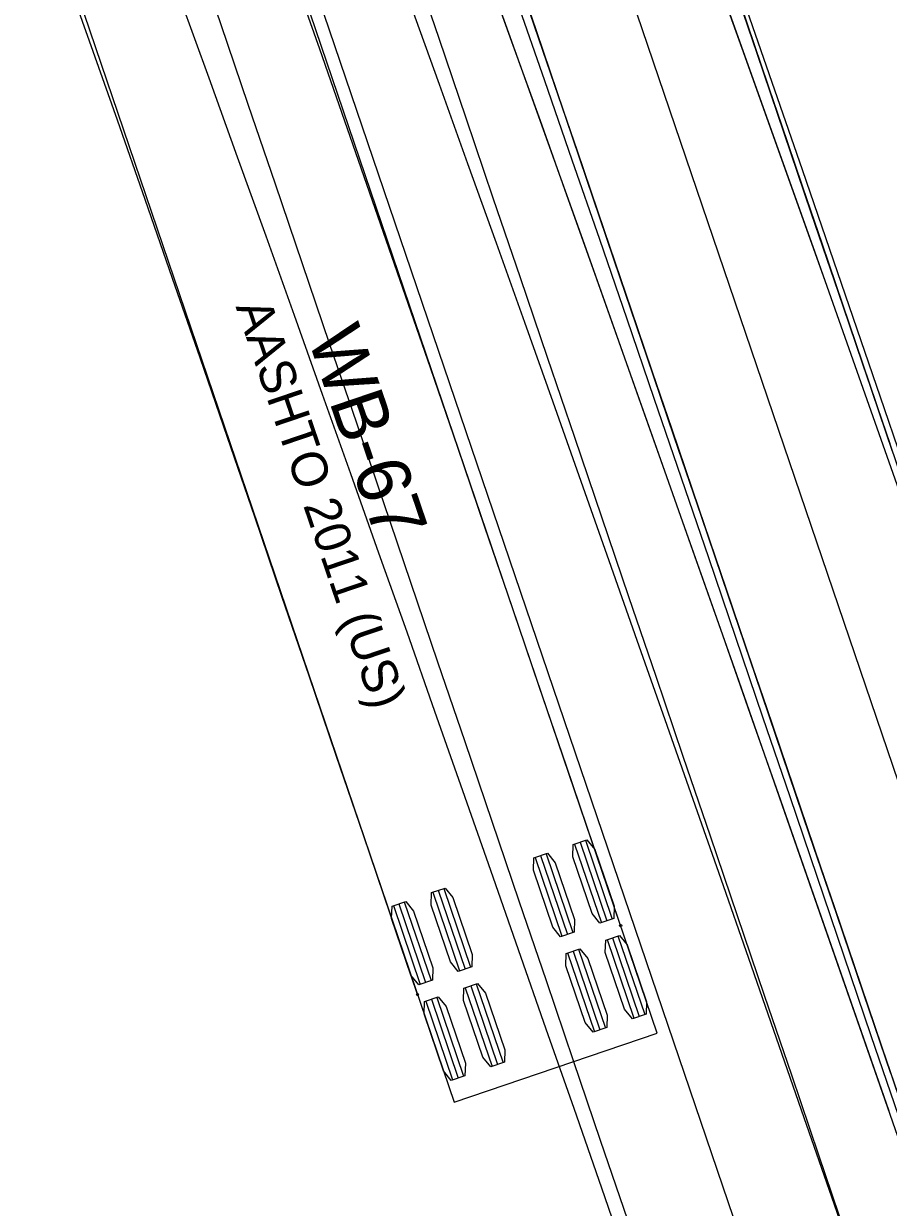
# Model space of a CAD drawing. Extents: x 916040 to 917457, y 328936 to 330267.
# Drawn here: x 916812.6 to 916846.87, y 329207.57 to 329254.51 of the extents above; entities that cross this region are included whole.
import ezdxf

# ---------------------------------------------------------------- set-up
doc = ezdxf.new("R2010")
doc.units = 0
for name, color, linetype in [('EB_RightontoSaco_WB67_v2', 7, 'Continuous'), ('NB_LeftontoRoute25_WB67', 7, 'Continuous'), ('NB_RightontoRoute25_WB67', 7, 'Continuous'), ('NB_ThruontoManchester_WB67', 7, 'Continuous'), ('SB_ThruontonSacoRd_WB67', 7, 'Continuous')]:
    doc.layers.add(name, color=color, linetype=linetype)

msp = doc.modelspace()

# ---------------------------------------------------------------- linework, layer by layer
at = {"layer": 'EB_RightontoSaco_WB67_v2'}
msp.add_line((916815.816, 329280.442), (916864.811, 329136.285), dxfattribs=at)
for points in [[(916819.347, 329257.622), (916820.42, 329254.467), (916821.492, 329251.31), (916822.565, 329248.153), (916823.639, 329244.995), (916824.712, 329241.836), (916825.786, 329238.677), (916826.86, 329235.518), (916827.933, 329232.358), (916829.007, 329229.198), (916830.081, 329226.038), (916831.156, 329222.878), (916832.23, 329219.717), (916833.304, 329216.557), (916834.378, 329213.396), (916835.452, 329210.235), (916836.527, 329207.074)], [(916827.973, 329257.101), (916829.049, 329253.935), (916830.125, 329250.77), (916831.201, 329247.605), (916832.276, 329244.441), (916833.351, 329241.277), (916834.427, 329238.114), (916835.502, 329234.951), (916836.577, 329231.788), (916837.651, 329228.626), (916838.726, 329225.463), (916839.801, 329222.301), (916840.876, 329219.139), (916841.95, 329215.977), (916843.025, 329212.815), (916844.1, 329209.653), (916845.174, 329206.492)], [(916818.803, 329255.495), (916819.938, 329252.362), (916821.068, 329249.227), (916822.195, 329246.09), (916823.319, 329242.952), (916824.438, 329239.811), (916825.555, 329236.67), (916826.669, 329233.527), (916827.78, 329230.382), (916828.889, 329227.236), (916829.995, 329224.09), (916831.099, 329220.942), (916832.2, 329217.793), (916833.3, 329214.643), (916834.399, 329211.493), (916835.495, 329208.341), (916836.59, 329205.189)], [(916827.931, 329255.252), (916829.066, 329252.106), (916830.196, 329248.96), (916831.323, 329245.812), (916832.446, 329242.663), (916833.566, 329239.513), (916834.682, 329236.362), (916835.796, 329233.211), (916836.906, 329230.059), (916838.015, 329226.906), (916839.121, 329223.752), (916840.224, 329220.598), (916841.326, 329217.444), (916842.426, 329214.288), (916843.524, 329211.133), (916844.62, 329207.977), (916845.715, 329204.821)]]:
    msp.add_lwpolyline(points, dxfattribs=at)
at = {"layer": 'NB_LeftontoRoute25_WB67'}
msp.add_line((916922.624, 329002.695), (916826.941, 329284.223), dxfattribs=at)
for points in [[(916820.466, 329308.249), (916821.712, 329305.145), (916822.946, 329302.037), (916824.17, 329298.925), (916825.385, 329295.81), (916826.59, 329292.692), (916827.786, 329289.571), (916828.974, 329286.447), (916830.154, 329283.321), (916831.327, 329280.192), (916832.494, 329277.061), (916833.654, 329273.929), (916834.808, 329270.795), (916835.956, 329267.659), (916837.1, 329264.521), (916838.238, 329261.382), (916839.372, 329258.242), (916840.502, 329255.101), (916841.628, 329251.958), (916842.75, 329248.815), (916843.869, 329245.67), (916844.984, 329242.525), (916846.097, 329239.379), (916847.206, 329236.232)], [(916822.723, 329307.431), (916823.938, 329304.292), (916825.132, 329301.146), (916826.306, 329297.992), (916827.459, 329294.831), (916828.592, 329291.662), (916829.704, 329288.486), (916830.796, 329285.304), (916831.875, 329282.131), (916832.953, 329278.96), (916834.03, 329275.792), (916835.106, 329272.626), (916836.182, 329269.461), (916837.258, 329266.298), (916838.332, 329263.135), (916839.407, 329259.974), (916840.481, 329256.813), (916841.555, 329253.654), (916842.629, 329250.494), (916843.702, 329247.336), (916844.776, 329244.177), (916845.849, 329241.019), (916846.923, 329237.861)], [(916831.852, 329257.343), (916832.923, 329254.192), (916833.994, 329251.039), (916835.066, 329247.886), (916836.138, 329244.733), (916837.21, 329241.579), (916838.282, 329238.424), (916839.354, 329235.27), (916840.426, 329232.115), (916841.498, 329228.96), (916842.571, 329225.805), (916843.643, 329222.649), (916844.716, 329219.494), (916845.788, 329216.338), (916846.861, 329213.183), (916847.933, 329210.027)], [(916831.376, 329255.36), (916832.502, 329252.229), (916833.624, 329249.096), (916834.743, 329245.961), (916835.859, 329242.825), (916836.972, 329239.687), (916838.082, 329236.548), (916839.189, 329233.408), (916840.294, 329230.267), (916841.397, 329227.124), (916842.498, 329223.981), (916843.597, 329220.837), (916844.693, 329217.692), (916845.789, 329214.546), (916846.882, 329211.399)]]:
    msp.add_lwpolyline(points, dxfattribs=at)
at = {"layer": 'NB_RightontoRoute25_WB67'}
msp.add_line((916922.624, 329002.695), (916826.941, 329284.223), dxfattribs=at)
for points in [[(916847.795, 329236.064), (916846.717, 329239.226), (916845.637, 329242.389), (916844.554, 329245.55), (916843.467, 329248.712), (916842.375, 329251.872), (916841.278, 329255.032), (916840.175, 329258.189), (916839.065, 329261.345), (916837.948, 329264.499), (916836.822, 329267.651), (916835.687, 329270.8), (916834.543, 329273.946), (916833.388, 329277.088), (916832.222, 329280.227), (916831.045, 329283.362), (916829.855, 329286.492), (916828.654, 329289.619), (916827.439, 329292.74), (916826.21, 329295.856), (916824.968, 329298.967), (916823.712, 329302.073), (916822.44, 329305.172), (916821.154, 329308.266)], [(916847.033, 329237.537), (916845.96, 329240.693), (916844.887, 329243.849), (916843.815, 329247.006), (916842.742, 329250.162), (916841.669, 329253.318), (916840.597, 329256.474), (916839.524, 329259.63), (916838.451, 329262.786), (916837.379, 329265.943), (916836.306, 329269.099), (916835.233, 329272.255), (916834.16, 329275.411), (916833.088, 329278.567), (916832.015, 329281.723), (916830.942, 329284.879), (916829.86, 329288.043), (916828.755, 329291.205), (916827.63, 329294.362), (916826.483, 329297.514), (916825.316, 329300.66), (916824.127, 329303.8), (916822.918, 329306.933)], [(916846.967, 329212.87), (916845.894, 329216.026), (916844.822, 329219.182), (916843.749, 329222.338), (916842.676, 329225.494), (916841.604, 329228.651), (916840.531, 329231.807), (916839.458, 329234.963), (916838.386, 329238.119), (916837.313, 329241.275), (916836.24, 329244.431), (916835.167, 329247.587), (916834.095, 329250.744), (916833.022, 329253.9), (916831.949, 329257.056)], [(916847.266, 329211.214), (916846.193, 329214.37), (916845.121, 329217.526), (916844.048, 329220.682), (916842.974, 329223.843), (916841.899, 329227.004), (916840.824, 329230.165), (916839.749, 329233.324), (916838.672, 329236.482), (916837.594, 329239.638), (916836.514, 329242.792), (916835.43, 329245.943), (916834.343, 329249.092), (916833.251, 329252.237), (916832.153, 329255.379)]]:
    msp.add_lwpolyline(points, dxfattribs=at)
at = {"layer": 'NB_ThruontoManchester_WB67'}
msp.add_line((916922.624, 329002.695), (916826.941, 329284.223), dxfattribs=at)
for points in [[(916822.108, 329308.997), (916823.333, 329305.862), (916824.537, 329302.72), (916825.721, 329299.57), (916826.885, 329296.412), (916828.028, 329293.247), (916829.151, 329290.075), (916830.253, 329286.895), (916831.336, 329283.717), (916832.414, 329280.545), (916833.492, 329277.376), (916834.568, 329274.209), (916835.644, 329271.043), (916836.72, 329267.879), (916837.795, 329264.716), (916838.87, 329261.555), (916839.944, 329258.394), (916841.018, 329255.233), (916842.092, 329252.074), (916843.166, 329248.915), (916844.239, 329245.756), (916845.313, 329242.598), (916846.386, 329239.44), (916847.459, 329236.283)], [(916821.091, 329306.698), (916822.331, 329303.592), (916823.561, 329300.482), (916824.78, 329297.369), (916825.989, 329294.252), (916827.19, 329291.132), (916828.382, 329288.009), (916829.566, 329284.884), (916830.742, 329281.757), (916831.912, 329278.627), (916833.075, 329275.496), (916834.232, 329272.362), (916835.383, 329269.227), (916836.529, 329266.09), (916837.67, 329262.952), (916838.806, 329259.812), (916839.938, 329256.671), (916841.066, 329253.53), (916842.189, 329250.387), (916843.31, 329247.243), (916844.427, 329244.098), (916845.541, 329240.952), (916846.652, 329237.806), (916847.761, 329234.659)], [(916830.811, 329256.925), (916831.939, 329253.795), (916833.064, 329250.662), (916834.184, 329247.529), (916835.302, 329244.393), (916836.416, 329241.256), (916837.527, 329238.118), (916838.636, 329234.978), (916839.742, 329231.838), (916840.846, 329228.696), (916841.948, 329225.553), (916843.048, 329222.409), (916844.145, 329219.264), (916845.241, 329216.119), (916846.336, 329212.973), (916847.429, 329209.826)], [(916832.387, 329255.768), (916833.459, 329252.615), (916834.53, 329249.463), (916835.602, 329246.309), (916836.674, 329243.156), (916837.746, 329240.002), (916838.818, 329236.847), (916839.89, 329233.692), (916840.962, 329230.538), (916842.035, 329227.382), (916843.107, 329224.227), (916844.179, 329221.072), (916845.252, 329217.916), (916846.324, 329214.761), (916847.397, 329211.605)]]:
    msp.add_lwpolyline(points, dxfattribs=at)
at = {"layer": 'SB_ThruontonSacoRd_WB67'}
for p, q in [((916837.707, 329214.478), (916820.652, 329264.659)), ((916812.604, 329261.924), (916829.659, 329211.743)), ((916834.433, 329221.973), (916835.495, 329218.849)), ((916834.65, 329222.047), (916835.712, 329218.923)), ((916834.867, 329222.121), (916835.929, 329218.996)), ((916832.871, 329221.443), (916833.933, 329218.318)), ((916833.088, 329221.516), (916834.15, 329218.392)), ((916833.305, 329221.59), (916834.367, 329218.466)), ((916828.816, 329220.064), (916829.878, 329216.94)), ((916829.033, 329220.138), (916830.095, 329217.013)), ((916829.25, 329220.212), (916830.311, 329217.087)), ((916827.253, 329219.533), (916828.315, 329216.409)), ((916827.47, 329219.607), (916828.532, 329216.482)), ((916827.687, 329219.681), (916828.749, 329216.556)), ((916835.721, 329218.186), (916836.782, 329215.062)), ((916835.938, 329218.26), (916836.999, 329215.135)), ((916836.154, 329218.334), (916837.216, 329215.209)), ((916834.158, 329217.655), (916835.22, 329214.531)), ((916834.375, 329217.729), (916835.437, 329214.605)), ((916834.592, 329217.803), (916835.654, 329214.678)), ((916830.103, 329216.277), (916831.165, 329213.152)), ((916830.32, 329216.351), (916831.382, 329213.226)), ((916830.537, 329216.424), (916831.599, 329213.3)), ((916828.758, 329215.82), (916829.819, 329212.695)), ((916828.975, 329215.893), (916830.036, 329212.769)), ((916828.541, 329215.746), (916829.602, 329212.621)), ((916829.659, 329211.743), (916837.707, 329214.478))]:
    msp.add_line(p, q, dxfattribs=at)
for points in [[(916828.211, 329216.004), (916827.137, 329219.164), (916826.063, 329222.323), (916824.989, 329225.482), (916823.914, 329228.639), (916822.838, 329231.795), (916821.76, 329234.948), (916820.679, 329238.1), (916819.595, 329241.248), (916818.507, 329244.394), (916817.414, 329247.536), (916816.315, 329250.675), (916815.21, 329253.81), (916814.097, 329256.941)], [(916836.259, 329218.739), (916835.185, 329221.899), (916834.111, 329225.059), (916833.036, 329228.219), (916831.96, 329231.38), (916830.882, 329234.54), (916829.801, 329237.701), (916828.718, 329240.861), (916827.63, 329244.02), (916826.538, 329247.178), (916825.44, 329250.336), (916824.335, 329253.491), (916823.223, 329256.645)]]:
    msp.add_lwpolyline(points, dxfattribs=at)
for points in [[(916834.38, 329221.955), (916834.921, 329222.139), (916835.233, 329221.757), (916835.998, 329219.508), (916835.983, 329219.015), (916835.441, 329218.831), (916835.13, 329219.213), (916834.365, 329221.462)], [(916832.817, 329221.424), (916833.359, 329221.608), (916833.671, 329221.226), (916834.435, 329218.977), (916834.421, 329218.484), (916833.879, 329218.3), (916833.567, 329218.682), (916832.803, 329220.931)], [(916828.762, 329220.046), (916829.303, 329220.23), (916829.615, 329219.848), (916830.38, 329217.598), (916830.365, 329217.105), (916829.824, 329216.921), (916829.512, 329217.303), (916828.747, 329219.553)], [(916827.2, 329219.515), (916827.741, 329219.699), (916828.053, 329219.317), (916828.818, 329217.067), (916828.803, 329216.574), (916828.261, 329216.39), (916827.95, 329216.772), (916827.185, 329219.022)], [(916835.667, 329218.168), (916836.208, 329218.352), (916836.52, 329217.97), (916837.285, 329215.72), (916837.27, 329215.228), (916836.729, 329215.043), (916836.417, 329215.425), (916835.652, 329217.675)], [(916834.104, 329217.637), (916834.646, 329217.821), (916834.958, 329217.439), (916835.722, 329215.189), (916835.708, 329214.697), (916835.166, 329214.513), (916834.855, 329214.894), (916834.09, 329217.144)], [(916830.049, 329216.259), (916830.591, 329216.443), (916830.902, 329216.061), (916831.667, 329213.811), (916831.652, 329213.318), (916831.111, 329213.134), (916830.799, 329213.516), (916830.034, 329215.766)], [(916828.487, 329215.728), (916829.028, 329215.912), (916829.34, 329215.53), (916830.105, 329213.28), (916830.09, 329212.787), (916829.549, 329212.603), (916829.237, 329212.985), (916828.472, 329215.235)]]:
    msp.add_lwpolyline(points, close=True, dxfattribs=at)
for centre in [(916836.259, 329218.739), (916828.211, 329216.004)]:
    msp.add_circle(centre, 0.0417, dxfattribs=at)

# ---------------------------------------------------------------- texts
for s, height, p in [('AASHTO 2011 (US)', 1.41667, (916820.996, 329243.285)), ('WB-67', 2.125, (916823.837, 329242.081))]:
    msp.add_text(s, height=height, rotation=288.7715, dxfattribs=at).set_placement(p)

doc.saveas('drawing.dxf')
